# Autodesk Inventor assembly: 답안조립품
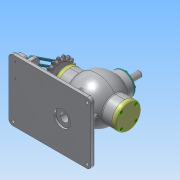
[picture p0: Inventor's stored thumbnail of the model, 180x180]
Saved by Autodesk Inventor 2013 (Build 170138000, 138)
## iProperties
Created: 2017-07
Part Number: 답안조립품
Document SubType Name: Assembly
Designer: Administrator
Author: Administrator
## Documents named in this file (20)
- C:\Users\Administrator\Desktop\370708V1022\답안조립품.iam
- C:\Users\Administrator\Desktop\370708V1022\본체.ipt
- C:\Users\Administrator\Desktop\370708V1022\고정핀.ipt
- C:\Users\Administrator\Desktop\370708V1022\너트 M8x1.ipt
- C:\Users\Administrator\Desktop\370708V1022\둥근머리 볼트 M4x8.ipt
- C:\Users\Administrator\Desktop\370708V1022\뒤커버.ipt
- C:\Users\Administrator\Desktop\370708V1022\베어링 6202.ipt
- C:\Users\Administrator\Desktop\370708V1022\본체커버.ipt
- C:\Users\Administrator\Desktop\370708V1022\볼트 M4x12.ipt
- C:\Users\Administrator\Desktop\370708V1022\스프로킷.ipt
- C:\Users\Administrator\Desktop\370708V1022\스프링.ipt
- C:\Users\Administrator\Desktop\370708V1022\슬라이드 커버.ipt
- C:\Users\Administrator\Desktop\370708V1022\슬라이드.ipt
- C:\Users\Administrator\Desktop\370708V1022\앞커버.ipt
- C:\Users\Administrator\Desktop\370708V1022\연결대.ipt
- C:\Users\Administrator\Desktop\370708V1022\오일실.ipt
- C:\Users\Administrator\Desktop\370708V1022\와셔 8x17.ipt
- C:\Users\Administrator\Desktop\370708V1022\와셔 ISO 7093 A.ipt
- C:\Users\Administrator\Desktop\370708V1022\축.ipt
- C:\Users\Administrator\Desktop\370708V1022\키 3 x 3 x 12.ipt
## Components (1 placed, 1 different names)
1. 고정핀:1
